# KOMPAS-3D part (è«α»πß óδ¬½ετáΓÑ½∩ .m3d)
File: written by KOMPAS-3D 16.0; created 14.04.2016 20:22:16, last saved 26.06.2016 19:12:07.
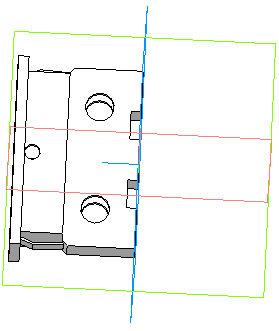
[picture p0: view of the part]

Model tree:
1. Эскиз:1
2. Операция выдавливания:1
     Расстояние 1 = 22
3. Эскиз:2
4. Операция выдавливания:2
     Расстояние 1 = 2
5. Эскиз:3
6. Вырезать элемент выдавливания:1
     Расстояние 1 = 2
7. Эскиз:5
8. Вырезать элемент выдавливания:3
     Расстояние 1 = 2.5
9. Эскиз:6
10. Вырезать элемент выдавливания:4
     Расстояние 1 = 2.5
11. Эскиз:7
12. Вырезать элемент выдавливания:5
     Расстояние 1 = 1.7
13. Эскиз:8
14. Вырезать элемент выдавливания:6
     Расстояние 1 = 1.7
15. Фаска:1
     Угол = 45; Длина 1 = 1; Длина 2 = 1
16. Фаска:2
     Угол = 45; Длина 1 = 1; Длина 2 = 1
17. Эскиз:9
18. Вырезать элемент выдавливания:7
     Расстояние 1 = 9
19. Эскиз:10
20. Вырезать элемент выдавливания:8
     Расстояние 1 = 11
21. Эскиз:11
22. Операция выдавливания:3
     Расстояние 1 = 1
23. Эскиз:12
24. Вырезать элемент выдавливания:9
     Расстояние 1 = 49
25. Эскиз:13
26. Вырезать элемент выдавливания:10
     Расстояние 1 = 49
27. Эскиз:15
28. Вырезать элемент выдавливания:12
     Расстояние 1 = 11
29. Эскиз:16
30. Операция выдавливания:4
     Расстояние 1 = 4; Расстояние 2 = 8
31. Вырезать элемент выдавливания:13
     Расстояние 1 = 4
32. Вырезать элемент выдавливания:14
     Расстояние 1 = 4
33. Эскиз:17
34. Операция выдавливания:5
     Расстояние 1 = 0.4
35. Эскиз:18
36. Операция выдавливания:6
     Расстояние 1 = 0.4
